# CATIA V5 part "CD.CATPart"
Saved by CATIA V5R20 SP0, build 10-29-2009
Part number: cd
Bounding box of the stored display mesh (mm): x 0 to 15, y -76.416 to 43.584, z 30.028 to 49.972
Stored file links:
  C:\Users\Willy\Documents\ThinkMotion\646\CD.CATPart
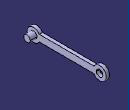
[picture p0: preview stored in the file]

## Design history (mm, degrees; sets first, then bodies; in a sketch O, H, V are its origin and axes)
Parameters
  `Longueur bièle` = 100 mm
Body1 (main body)
  Sketch1 on yz-plane, origin (0, 0, 0), H (0, 1, 0), V (0, 0, 1)
    line L1 (-57.7553, 45) -> (24.9242, 45)
    line L2 (-57.7553, 35) -> (24.9242, 35)
    axis line L3 (-76.4155, 40) -> (33.5845, 40)
    point P5 (-76.4155, 40)
    arc A1 centre (-66.4155, 40) radius 10 from (-57.7553, 45) to (-57.7553, 35) ccw
    point P7 (-66.4155, 40)
    arc A2 centre (33.5845, 40) radius 10 from (24.9242, 35) to (24.9242, 45) ccw
    point P8 (33.5845, 40)
    circle A3 centre (33.5845, 40) radius 5
    circle A4 centre (-66.4155, 40) radius 5
    distance L2 L1 = 10
    radius A1 = 10
    radius A2 = 10
    distance P8 P7 = 100 {= `Longueur bièle`}
    radius A3 = 5
    radius A4 = 5
    horizontal: L1 H, L2 H, L3 H
    coincidence: A1 P5, P7 L3, P8 L3
    symmetry: L2 L1 L3
  Pad1: profile Sketch1, direction (1, 0, 0), length 5
  Sketch2 on start face of Pad1, origin (0, 0, 0), H (0, -1, 0), V (0, 0, 1)
    circle A1 centre (66.4155, 40) radius 5
    reference projected circle E1 centre (66.4155, 40) radius 5 from edge [face of Pad1 from Sketch1.A4 | start face of Pad1]
    coincidence: E1 A1
  Pad2: profile Sketch2, direction (1, 0, 0), length 15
